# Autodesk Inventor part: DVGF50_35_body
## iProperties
Created: 2010-04
Part Number: DVGF50_35_body
Document SubType Name: Modeling
Designer: TB
Mass: 507.874 g
Surface Area: 1102.64 cm^2
Volume: 507.874 cm^3
Density: 1 g/cm^3
Author: TB
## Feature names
1. Kropp [Revolution]
2. Chamfer
3. Extrusion2
4. Hole1
5. Revolution2
6. Hole2
7. Fillet1
8. Extrusion3
9. Hole3
